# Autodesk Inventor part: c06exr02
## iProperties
Shininess: 77.0
Length Units: 11269
Angle Units: 11279
Time Units: 11290
Mass Units: 11283
Length Display Precision: 3
Angle Display Precision: 2
Created: 2001-12
Part Number: c06exr02
Document SubType Name: Modeling
Density: 1 g/cm^3
Density: 0.0
Volumn: 0.0
Area: 0.0
PropertySet Name: Model Information
Control State: 0
Master: False
Checked Out: False
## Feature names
1. Extrusion1
2. Extrusion2
3. Extrusion3
4. Extrusion4
5. Extrusion6
6. Hole1
7. Mirror1
8. Fillet1
9. Hole2
10. Hole3
11. Hole4
